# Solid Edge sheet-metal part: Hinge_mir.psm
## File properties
Author: m_hel
Template: Iso Metric Sheet Metal.psm
Last saved by: m_hel
Revision: 4
Application: Solid Edge
Accuracy: 0,990
Material Thickness: 3,00 mm
Bend Radius: 1,00 mm
Relief Width: 1,00 mm
Relief Length: 0,00 mm
Neutral Factor: 0,330
Minimum Arc Length: 0,10 mm
Deviational Tolerance: 0,10 mm
Username: m_hel
Material: Chrome
Face Style: Chrome
Fill Style: Normal
Virtual Style: Normal
Grouping: Uncategorized
LibraryName: Custom Materials
Coef. of Thermal Exp: 0.0
Thermal Conductivity: 0.0
Specific Heat: 0.0
Modulus of Elasticity: 0.0
Poisson's Ratio: 0.0
Yield Stress: 0.0
Ultimate Stress: 0.0
Elongation: 0.0
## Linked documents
Hinge.psm
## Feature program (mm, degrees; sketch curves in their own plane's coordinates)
part copy "CopiedPart_1"
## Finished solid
Body 1: solid body, 18 faces, 44 edges, 28 vertices.
  Faces by surface: plane 10, cylinder 8
  Edges by curve: line 28, circle 16
Bounding box of the edges (mm): 49.233 x 63.000 x 16.000, from (-24.6165, -13, -8) to (24.6165, 50, 8).
Cylindrical faces by radius (mm): R1 x1, R2 x4, R4 x1, R5 x1, R8 x1
Planar faces by outward normal: +x 1, +y 1, +z 1, -x 1, -y 2, -z 1, oblique 3
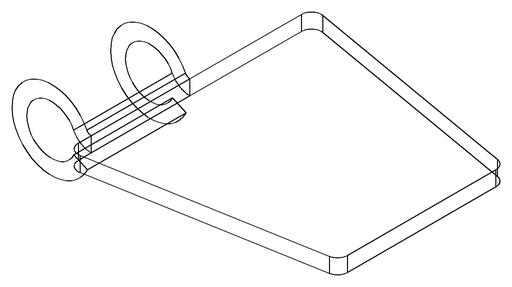
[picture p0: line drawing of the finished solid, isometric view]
